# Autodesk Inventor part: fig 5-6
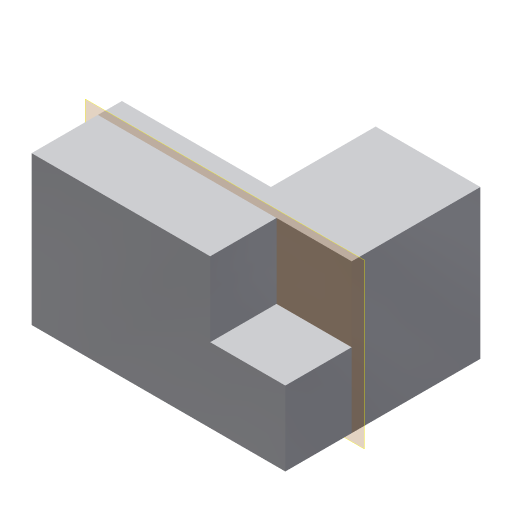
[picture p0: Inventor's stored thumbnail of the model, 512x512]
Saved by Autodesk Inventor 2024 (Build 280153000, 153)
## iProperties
Created: 2010-02
Part Number: fig 5-6
Document SubType Name: Modeling
Designer: CADSoft
Density: 1 g/cm^3
Material: Generic
Appearance: Default
Author: CADSoft
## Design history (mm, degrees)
sketch "Sketch1"
  geometry: L1 (0, 26.227)-(0, 12.145); L2 (0, 12.145)-(-20.026, 12.145); L3 (-20.026, 12.145)-(-20.026, 0); L4 (-20.026, 0)-(14.083, 0); L5 (14.083, 0)-(14.083, 26.227); L6 (14.083, 26.227)-(0, 26.227); 1 further point
  constraints: 12 end point
extrude "Extrusion1" new body sketch "Sketch1" distance "d0" = 20; taper "d1" = 0 deg
sketch "Sketch2"
  geometry: L1 (14.083, 0)-(3.983, 0); L2 (3.983, 0)-(3.983, 8.922); L3 (3.983, 8.922)-(14.083, 8.922); L4 (14.083, 8.922)-(14.083, 0); 1 further point
  constraints: 8 end point
extrude "Extrusion2" cut sketch "Sketch2" distance "d2" = 10; taper "d3" = 0 deg
workplane "Work Plane1"
body "Solid1"
